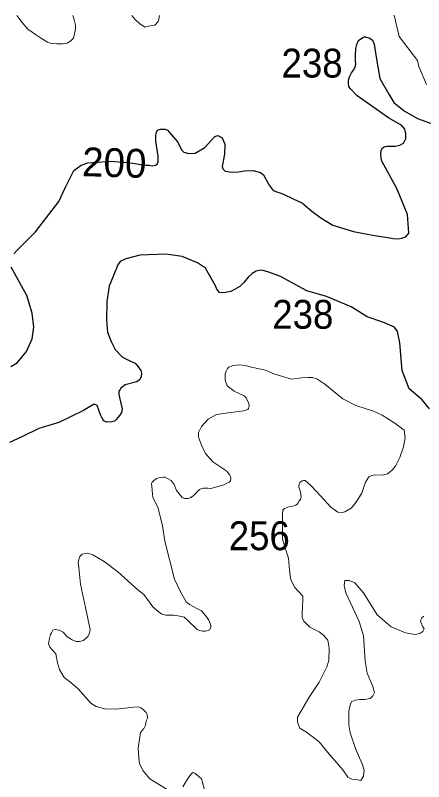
# Model space of a CAD drawing. Extents: x 445.4 to 500, y 8728.7 to 8784.
# Drawn here: x 481.821 to 484.088, y 8779.753 to 8784.003 of the extents above; entities that cross this region are included whole.
import ezdxf
from ezdxf.enums import TextEntityAlignment as Align

# ---------------------------------------------------------------- set-up
doc = ezdxf.new("R2010")
doc.units = 0
doc.header["$LTSCALE"] = 0.064
doc.layers.add('1', color=7, linetype='Continuous', lineweight=25)
doc.layers.add('2', color=7, linetype='Continuous', lineweight=13)
doc.layers.add('21', color=7, linetype='Continuous')
doc.layers.add('61', color=7, linetype='Continuous')

msp = doc.modelspace()

# ---------------------------------------------------------------- linework, layer by layer
at = {"layer": '1'}
for points in [[(483.8828, 8783.2775), (483.8946, 8783.2775), (483.911, 8783.2775), (483.9297, 8783.2775), (483.9555, 8783.2822), (483.9555, 8783.2822), (483.9766, 8783.2939), (483.9766, 8783.2939), (483.9883, 8783.3197), (483.9883, 8783.3478), (483.9836, 8783.3712), (483.9672, 8783.3922), (483.8922, 8783.4344), (483.7188, 8783.5561), (483.6787, 8783.5973), (483.6729, 8783.6089), (483.6706, 8783.6286), (483.6706, 8783.6425), (483.6752, 8783.661), (483.6868, 8783.6842), (483.6973, 8783.6981), (483.7054, 8783.712), (483.7112, 8783.7317), (483.7089, 8783.7502), (483.7089, 8783.7827), (483.7112, 8783.8186), (483.7158, 8783.8418), (483.7251, 8783.8638), (483.7495, 8783.88), (483.7622, 8783.8846), (483.768, 8783.8823), (483.7889, 8783.8754), (483.8028, 8783.8649), (483.8133, 8783.8429), (483.8249, 8783.7595), (483.8446, 8783.6529), (483.8945, 8783.566), (483.9223, 8783.5185), (483.9797, 8783.4726), (484.054, 8783.4297), (484.1352, 8783.4019)], [(481.8118, 8782.6796), (481.8286, 8782.6992), (481.9325, 8782.8016), (482.0616, 8782.9712), (482.0985, 8783.0492), (482.1463, 8783.1417), (482.187, 8783.1711), (482.2235, 8783.1852), (482.3526, 8783.1936), (482.3933, 8783.1908), (482.4466, 8783.1866), (482.4944, 8783.1796), (482.5266, 8783.174), (482.5449, 8783.1725), (482.5631, 8783.1711), (482.5828, 8783.1683), (482.5996, 8783.1711), (482.608, 8783.1782), (482.6137, 8783.1894), (482.6137, 8783.2216), (482.601, 8783.3043), (482.6007, 8783.3343), (482.6021, 8783.3497), (482.6105, 8783.3652), (482.626, 8783.3708), (482.6526, 8783.3722), (482.6653, 8783.3652), (482.7214, 8783.3007), (482.7453, 8783.2544), (482.7565, 8783.2432), (482.7761, 8783.239), (482.7958, 8783.2362), (482.8183, 8783.2376), (482.873, 8783.2698), (482.9277, 8783.3301), (482.9446, 8783.3357), (482.9446, 8783.3357), (482.9684, 8783.3231), (482.9839, 8783.288), (482.9811, 8783.232), (482.9684, 8783.1647), (482.9727, 8783.1521), (482.9853, 8783.1394), (483.0246, 8783.1338), (483.0597, 8783.1352), (483.0934, 8783.1408), (483.1404, 8783.1413), (483.1825, 8783.1315), (483.1993, 8783.1188), (483.2302, 8783.06), (483.2513, 8783.0305), (483.3088, 8783.0109), (483.3635, 8782.9857), (483.4141, 8782.9604), (483.4674, 8782.917), (483.5165, 8782.8791), (483.5839, 8782.8384), (483.699, 8782.8048), (483.8141, 8782.781), (483.8992, 8782.768), (483.9189, 8782.7652), (483.9455, 8782.7624), (483.9666, 8782.7666), (483.989, 8782.775), (484.0045, 8782.7947), (483.9982, 8782.899), (483.9396, 8783.0418), (483.8547, 8783.1932), (483.8524, 8783.212), (483.85, 8783.2354), (483.8524, 8783.2518), (483.8571, 8783.2658), (483.8688, 8783.2728), (483.8828, 8783.2775)], [(484.1204, 8781.8207), (484.0787, 8781.8707), (484.007, 8781.9306), (483.9686, 8782.0339), (483.9553, 8782.1872), (483.9419, 8782.2488), (483.9252, 8782.2732), (483.8602, 8782.3015), (483.7734, 8782.3315), (483.6851, 8782.3865), (483.5483, 8782.4431), (483.4399, 8782.4748), (483.292, 8782.5539), (483.2223, 8782.581), (483.1881, 8782.5893), (483.1739, 8782.5881), (483.1586, 8782.5846), (483.135, 8782.5716), (483.1137, 8782.5515), (483.0901, 8782.5209), (483.0665, 8782.4996), (483.0381, 8782.4831), (483.0169, 8782.4713), (482.9873, 8782.4666), (482.9649, 8782.4643), (482.9543, 8782.4666), (482.9401, 8782.4843), (482.9318, 8782.5032), (482.8763, 8782.6011), (482.8326, 8782.6306), (482.7468, 8782.6662), (482.657, 8782.6791), (482.5118, 8782.6721), (482.4338, 8782.6532), (482.4031, 8782.6378), (482.3901, 8782.619), (482.3417, 8782.501), (482.3284, 8782.4164), (482.3261, 8782.3114), (482.332, 8782.2466), (482.352, 8782.1935), (482.3757, 8782.1487), (482.4158, 8782.1074), (482.4571, 8782.0873), (482.4859, 8782.0736), (482.5025, 8782.0535), (482.5178, 8782.0323), (482.5214, 8782.0181), (482.5202, 8781.9981), (482.5107, 8781.9816), (482.4954, 8781.9698), (482.4304, 8781.9533), (482.4068, 8781.9356), (482.4033, 8781.9285), (482.395, 8781.9191), (482.395, 8781.9025), (482.3985, 8781.8837), (482.4139, 8781.8212), (482.4099, 8781.8003), (482.4005, 8781.785), (482.3899, 8781.772), (482.3792, 8781.759), (482.371, 8781.7531), (482.3556, 8781.7484), (482.3273, 8781.7472), (482.3119, 8781.7543), (482.3084, 8781.7602), (482.3001, 8781.7732), (482.2942, 8781.7873), (482.2741, 8781.8392), (482.2647, 8781.8451), (482.2552, 8781.8439), (482.1986, 8781.8109), (482.0616, 8781.7449), (481.9517, 8781.7107), (481.8576, 8781.6656), (481.7879, 8781.6337)], [(481.7963, 8782.055), (481.83, 8782.076), (481.8819, 8782.1391), (481.9145, 8782.2088), (481.923, 8782.2732), (481.9145, 8782.3518), (481.8837, 8782.4485), (481.798, 8782.6069)]]:
    msp.add_lwpolyline(points, dxfattribs=at)
at = {"layer": '2'}
for points in [[(481.8283, 8784.0016), (481.8583, 8783.9631), (481.8909, 8783.9263), (481.9375, 8783.8924), (481.9658, 8783.874), (481.9997, 8783.8542), (482.0209, 8783.8471), (482.0492, 8783.8443), (482.0845, 8783.8443), (482.1085, 8783.8485), (482.1297, 8783.8612), (482.1439, 8783.8768), (482.1495, 8783.8994), (482.1538, 8783.9277), (482.1538, 8783.9475), (482.1495, 8783.9701), (482.1439, 8783.9899), (482.1394, 8784.0018)], [(482.4681, 8784.002), (482.4859, 8783.98), (482.5128, 8783.956), (482.541, 8783.9376), (482.5594, 8783.9419), (482.5948, 8783.9475), (482.6131, 8783.9687), (482.6174, 8783.9815), (482.6209, 8784.002)], [(483.9241, 8784.0027), (483.9518, 8783.8856), (484.0539, 8783.7515), (484.0608, 8783.7194), (484.1026, 8783.6184)], [(482.9054, 8781.3788), (482.9789, 8781.3987), (483.0083, 8781.414), (483.016, 8781.4217), (483.0173, 8781.4319), (483.0173, 8781.4383), (483.0121, 8781.4523), (482.9943, 8781.4753), (482.9176, 8781.5263), (482.8767, 8781.5735), (482.8548, 8781.6186), (482.8382, 8781.6633), (482.8369, 8781.6888), (482.8548, 8781.7233), (482.8906, 8781.7628), (482.9379, 8781.7883), (483.0017, 8781.7986), (483.0886, 8781.81), (483.1116, 8781.8164), (483.1155, 8781.8228), (483.118, 8781.8381), (483.1167, 8781.8496), (483.1078, 8781.8713), (483.1001, 8781.8828), (483.0912, 8781.893), (483.035, 8781.9185), (482.9967, 8781.9487), (482.9852, 8781.9793), (482.9852, 8781.9921), (482.9865, 8782.0125), (482.9903, 8782.0291), (482.998, 8782.0444), (483.0069, 8782.0521), (483.0299, 8782.061), (483.067, 8782.0648), (483.104, 8782.0585), (483.1398, 8782.0495), (483.2101, 8782.0355), (483.2561, 8782.0138), (483.3534, 8781.9852), (483.4106, 8781.9921), (483.445, 8781.9943), (483.4702, 8781.9943), (483.4953, 8781.9875), (483.5388, 8781.9577), (483.6396, 8781.8754), (483.7106, 8781.8388), (483.809, 8781.8068), (483.8571, 8781.7862), (483.9281, 8781.7405), (483.9785, 8781.7016), (483.9853, 8781.6604), (483.9762, 8781.6101), (483.9556, 8781.5506), (483.9327, 8781.5072), (483.9121, 8781.4797), (483.8869, 8781.4592), (483.8571, 8781.4523), (483.8182, 8781.4546), (483.7999, 8781.45), (483.7838, 8781.4431), (483.7655, 8781.4134), (483.7448, 8781.3525), (483.7082, 8781.2953), (483.6853, 8781.2702), (483.6509, 8781.2496), (483.6349, 8781.245), (483.612, 8781.2473), (483.5731, 8781.2747), (483.5158, 8781.3388), (483.4632, 8781.3937), (483.4445, 8781.411), (483.4303, 8781.4226), (483.4213, 8781.4239), (483.4135, 8781.4213), (483.4135, 8781.4213), (483.3993, 8781.4123), (483.3968, 8781.4046), (483.3955, 8781.3878), (483.4045, 8781.3581), (483.4084, 8781.3323), (483.4084, 8781.3323), (483.4032, 8781.3181), (483.3955, 8781.3078), (483.3916, 8781.3001), (483.3851, 8781.2923), (483.3774, 8781.2859), (483.367, 8781.282), (483.367, 8781.282), (483.3335, 8781.2755), (483.3154, 8781.2678), (483.3063, 8781.2588), (483.3038, 8781.2381), (483.3038, 8781.2046), (483.3038, 8781.0988), (483.3167, 8781.0555), (483.3374, 8780.9922), (483.3425, 8780.9264), (483.3503, 8780.8723), (483.3723, 8780.8297), (483.4162, 8780.7819)], [(482.091, 8780.331), (482.0655, 8780.3757), (482.054, 8780.4114), (482.0463, 8780.4625), (482.0131, 8780.4982), (482.0053, 8780.5182), (482.0092, 8780.5399), (482.0168, 8780.5692), (482.0207, 8780.5782), (482.0296, 8780.5935), (482.0424, 8780.596), (482.0424, 8780.596), (482.0641, 8780.5935), (482.0871, 8780.582), (482.1088, 8780.5565), (482.1369, 8780.5399), (482.1587, 8780.5309), (482.1765, 8780.5309), (482.1995, 8780.5361), (482.2225, 8780.559), (482.2328, 8780.5756), (482.2366, 8780.596), (482.211, 8780.7198), (482.1817, 8780.8475), (482.1727, 8780.9403), (482.1701, 8780.9671), (482.1727, 8780.9849), (482.1753, 8780.9926), (482.1791, 8781.0015), (482.1842, 8781.0079), (482.1919, 8781.0143), (482.2021, 8781.0168), (482.2238, 8781.0194), (482.2506, 8781.0105), (482.3133, 8780.9747), (482.3899, 8780.916), (482.5011, 8780.8165), (482.535, 8780.7913), (482.5849, 8780.7224), (482.6143, 8780.6969), (482.6347, 8780.6815), (482.6564, 8780.6764), (482.6833, 8780.6764), (482.6999, 8780.6764), (482.7114, 8780.6752), (482.7331, 8780.6713), (482.7574, 8780.665), (482.7753, 8780.6509), (482.8302, 8780.5973), (482.843, 8780.5909), (482.8609, 8780.5884), (482.8762, 8780.5884), (482.8915, 8780.5909), (482.8979, 8780.5948), (482.8979, 8780.5948), (482.9056, 8780.6088), (482.9056, 8780.6177), (482.903, 8780.6305), (482.8941, 8780.6484), (482.8762, 8780.6752), (482.8545, 8780.7007), (482.8277, 8780.7135), (482.7868, 8780.7351), (482.7689, 8780.7505), (482.7382, 8780.8053), (482.7037, 8780.8755), (482.6513, 8781.087), (482.6372, 8781.1713), (482.6128, 8781.2703), (482.5847, 8781.3303), (482.5809, 8781.3686), (482.5783, 8781.3928), (482.577, 8781.4005), (482.577, 8781.4069), (482.5809, 8781.4145), (482.5885, 8781.4222), (482.5962, 8781.4286), (482.6051, 8781.4337), (482.6166, 8781.4388), (482.6294, 8781.4401), (482.6409, 8781.4413), (482.6499, 8781.4413), (482.6652, 8781.435), (482.6856, 8781.4235), (482.7023, 8781.4005), (482.715, 8781.3686), (482.7317, 8781.3482), (482.747, 8781.329), (482.7598, 8781.3226), (482.7687, 8781.3226), (482.7789, 8781.3239), (482.7904, 8781.3277), (482.8058, 8781.3367), (482.816, 8781.3443), (482.8237, 8781.3533), (482.8339, 8781.3635), (482.8428, 8781.3724), (482.8505, 8781.3775), (482.8658, 8781.3801), (482.8888, 8781.3801), (482.9054, 8781.3788)], [(483.4162, 8780.7819), (483.4162, 8780.7605), (483.4123, 8780.6883), (483.4136, 8780.6638), (483.4226, 8780.6431), (483.4562, 8780.6096), (483.5066, 8780.5838), (483.5311, 8780.5657), (483.5557, 8780.5373), (483.5634, 8780.4935), (483.5609, 8780.4255), (483.5506, 8780.3907), (483.5067, 8780.3055), (483.4563, 8780.2268), (483.387, 8780.1113), (483.387, 8780.0835), (483.401, 8780.05), (483.4373, 8780.0277), (483.507, 8779.9748), (483.555, 8779.9144), (483.6387, 8779.8196), (483.6666, 8779.7778), (483.689, 8779.7667), (483.7197, 8779.7639), (483.738, 8779.7602), (483.7529, 8779.7832), (483.7577, 8779.8173), (483.7456, 8779.8513), (483.7115, 8779.9316), (483.6798, 8780.0241), (483.6725, 8780.0679), (483.6725, 8780.1433), (483.6822, 8780.1847), (483.6895, 8780.1968), (483.7066, 8780.2041), (483.7334, 8780.209), (483.7602, 8780.209), (483.7899, 8780.2138), (483.7899, 8780.2138), (483.8058, 8780.2297), (483.8138, 8780.2483), (483.8058, 8780.2801), (483.774, 8780.3543), (483.7634, 8780.4206), (483.7527, 8780.5611), (483.7295, 8780.6415), (483.6552, 8780.8006), (483.6472, 8780.8403), (483.6472, 8780.8403), (483.6499, 8780.8695), (483.6499, 8780.8695), (483.6737, 8780.8695), (483.7056, 8780.8562), (483.7534, 8780.8006), (483.8303, 8780.6786), (483.9073, 8780.6124), (483.9869, 8780.5779), (484.04, 8780.57), (484.0665, 8780.5753), (484.0833, 8780.5856), (484.091, 8780.5997), (484.0833, 8780.6126), (484.0692, 8780.6408), (484.0718, 8780.6511), (484.0769, 8780.6614), (484.0885, 8780.6717)], [(482.6787, 8779.7012), (482.5668, 8779.7684), (482.531, 8779.813), (482.5093, 8779.8527), (482.5055, 8779.8846), (482.5029, 8779.9382), (482.5093, 8779.9893), (482.5157, 8780.0263), (482.5336, 8780.048), (482.5425, 8780.0659), (482.5476, 8780.0901), (482.554, 8780.1054), (482.5527, 8780.1258), (482.5476, 8780.1373), (482.5297, 8780.1539), (482.5182, 8780.1629), (482.5042, 8780.168), (482.4786, 8780.1654), (482.379, 8780.1552), (482.3163, 8780.1565), (482.2686, 8780.1702), (482.2405, 8780.1893), (482.169, 8780.2672), (482.1294, 8780.3029), (482.091, 8780.331)], [(482.8702, 8779.7075), (482.8542, 8779.7681), (482.8415, 8779.7798), (482.8276, 8779.7915), (482.817, 8779.8011), (482.8085, 8779.8043), (482.7989, 8779.7979), (482.7925, 8779.7894), (482.7819, 8779.7756), (482.75, 8779.7246)]]:
    msp.add_lwpolyline(points, dxfattribs=at)

# ---------------------------------------------------------------- texts
at = {"layer": '21', "width": 0.95}
for s, p in [('238', (483.2986, 8783.6577)), ('256', (483.0055, 8781.0368))]:
    msp.add_text(s, height=0.16, dxfattribs=at).set_placement(p)
msp.add_text('238', height=0.16, dxfattribs=at).set_placement((483.5864, 8782.2646), align=Align.RIGHT)
at = {"layer": '61'}
msp.add_text('200', height=0.16, rotation=358.26, dxfattribs=at).set_placement((482.3678, 8783.1058), align=Align.CENTER)

doc.saveas('drawing.dxf')
